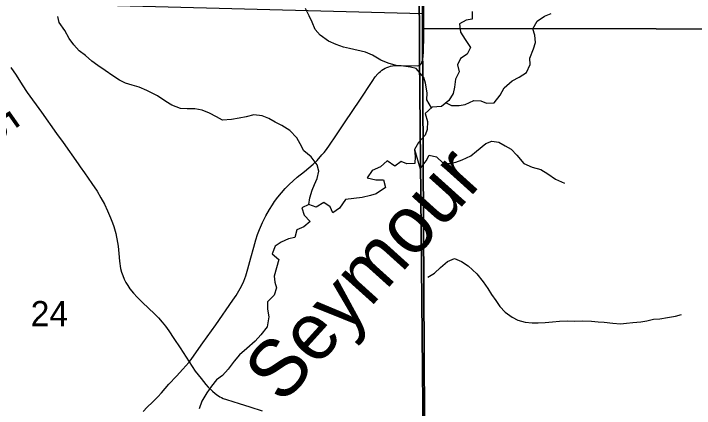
# Model space of a CAD drawing. Extents: x 1874609 to 2204689, y 815661 to 1281160.
# Drawn here: x 2009363 to 2015341, y 1005693 to 1009164 of the extents above; entities that cross this region are included whole.
import ezdxf

# ---------------------------------------------------------------- set-up
doc = ezdxf.new("R2010")
doc.units = 0
for name, color, linetype in [('GM_X_County_Road', 7, 'Continuous'), ('GM_X_County_Road_Text', 7, 'Continuous'), ('GM_X_Minor_River', 7, 'Continuous'), ('GM_X_Minor_River_Text', 7, 'Continuous'), ('GM_X_Section', 7, 'Continuous'), ('GM_X_Section_Text', 7, 'Continuous'), ('GM_X_Township', 7, 'Continuous'), ('GM_X_Township_Road', 7, 'Continuous')]:
    doc.layers.add(name, color=color, linetype=linetype)

msp = doc.modelspace()

# ---------------------------------------------------------------- linework, layer by layer
at = {"layer": 'GM_X_County_Road'}
for points in [[(2009340, 1008689.6), (2009385.4, 1008621.4), (2009438, 1008538.4), (2009483.6, 1008470.2), (2009607.4, 1008296.7), (2009739.6, 1008110), (2009797.7, 1008030.5), (2009929.1, 1007842.9), (2009948.2, 1007816.9), (2009985.9, 1007764), (2010050.9, 1007669.7), (2010096.2, 1007601.5), (2010129.5, 1007545.4), (2010160.3, 1007487.9), (2010188.8, 1007429.2), (2010215.2, 1007369.7), (2010232.9, 1007324.4), (2010242.7, 1007293.6), (2010259.6, 1007230.5), (2010276.7, 1007151), (2010281.4, 1007119.1), (2010286.6, 1007054.2), (2010293.3, 1006988.7), (2010303, 1006923.7), (2010310.4, 1006891.4), (2010321.1, 1006860.1), (2010334.5, 1006829.9), (2010349.6, 1006800.7), (2010366.4, 1006772.5), (2010385.1, 1006745.5), (2010415.8, 1006707.2), (2010448.6, 1006670.8), (2010494.6, 1006624.1), (2010601.1, 1006522.9), (2010634.9, 1006488.4), (2010667, 1006452.4), (2010697.6, 1006414.5), (2010726.3, 1006375.3), (2010771.6, 1006308.1), (2010825, 1006226.2), (2010904.8, 1006101.4)], [(2010904.8, 1006101.4), (2010930.8, 1006060.8), (2010959, 1006020.5), (2011008.8, 1005955.1), (2011050.3, 1005904), (2011072.6, 1005879.5), (2011108.5, 1005845.5), (2011133.4, 1005824.1), (2011146.3, 1005813.8), (2011174, 1005795.2), (2011188.6, 1005787.5), (2011203.6, 1005780.7), (2011233.9, 1005769.6), (2011343.3, 1005734.7), (2011437.3, 1005705.6), (2011546.5, 1005671.2)]]:
    msp.add_lwpolyline(points, dxfattribs=at)
at = {"layer": 'GM_X_Minor_River'}
for points in [[(2013032, 1008335.8), (2012991, 1008404.8), (2012995.2, 1008468.9), (2012981.5, 1008551.2), (2012965.7, 1008603.5), (2012897.8, 1008680), (2012847.7, 1008694.3), (2012785.6, 1008700.6), (2012721.5, 1008706.9), (2012651.4, 1008727.2), (2012589.3, 1008755.6), (2012513.3, 1008800.1), (2012453.3, 1008824.4), (2012313.1, 1008857.2), (2012261, 1008869.4), (2012197, 1008891.8), (2012126.9, 1008922.2), (2012054.9, 1008974.7), (2012011, 1009025), (2011985.2, 1009089.3), (2011959.3, 1009145.6), (2011927.5, 1009209.9)], [(2013390.7, 1009183.4), (2013390.4, 1009115.2), (2013336.3, 1009107.4), (2013278, 1009073.5), (2013287.8, 1009001.3), (2013329.7, 1008936.9), (2013375.5, 1008866.5), (2013347.2, 1008808.4), (2013287, 1008768.6), (2013260.7, 1008712.5), (2013276.5, 1008652.2), (2013242.2, 1008586.2), (2013236, 1008516), (2013223.7, 1008461.9), (2013185.4, 1008399.9), (2013121.1, 1008348), (2013038.9, 1008342.3), (2012978.6, 1008284.4), (2012998.3, 1008214.1), (2012994.1, 1008145.9), (2012977.9, 1008095.8), (2012917.5, 1008029.9), (2012883.2, 1007967.9)], [(2013160.4, 1008379.7), (2013209.3, 1008355.6), (2013275.5, 1008355.3), (2013327.6, 1008365.1), (2013403.9, 1008398.9), (2013466, 1008396.6), (2013516.1, 1008376.3), (2013582.3, 1008380), (2013636.6, 1008448), (2013670.9, 1008510.1), (2013741.3, 1008573.9), (2013801.5, 1008603.8), (2013867.8, 1008647.6), (2013898.2, 1008715.7), (2013896.3, 1008771.9), (2013928.7, 1008854), (2013947, 1008910.1), (2013941.2, 1008974.3), (2013923.3, 1009030.5), (2013959.6, 1009098.6), (2014025.9, 1009140.4), (2014082.2, 1009164.2)], [(2011955.4, 1007486.5), (2011963.7, 1007544.7), (2011983.9, 1007610.8), (2012004.2, 1007660.8), (2012028.4, 1007712.9), (2012044.7, 1007779), (2012028.8, 1007835.2), (2011977, 1007903.7), (2011911, 1007956.1), (2011879.1, 1008018.5), (2011851.3, 1008070.8), (2011789.3, 1008135.2), (2011717.3, 1008179.7), (2011661.3, 1008210), (2011603.3, 1008242.4), (2011547.3, 1008266.7), (2011473.1, 1008273.1), (2011404.9, 1008257.3), (2011342.7, 1008243.5), (2011276.5, 1008233.8), (2011196.3, 1008228.1), (2011146.3, 1008256.5), (2011082.3, 1008288.8), (2011018.3, 1008315.2), (2010954.1, 1008325.5), (2010888, 1008327.8), (2010827.9, 1008330.1), (2010751.8, 1008360.5), (2010699.8, 1008390.8), (2010625.8, 1008441.3), (2010531.8, 1008487.9), (2010465.7, 1008516.3), (2010403.6, 1008534.6), (2010345.6, 1008552.9), (2010293.6, 1008579.2), (2010235.6, 1008615.6), (2010167.6, 1008664), (2010103.6, 1008708.5), (2010051.6, 1008746.8), (2009993.7, 1008795.2), (2009939.7, 1008837.6), (2009891.8, 1008890), (2009849.9, 1008946.3), (2009814, 1009014.7), (2009764.2, 1009085.1), (2009752.3, 1009137.3)], [(2012883.2, 1007967.9), (2012932.7, 1007799.1), (2012985.1, 1007869.1), (2013013.3, 1007919.2), (2013075.4, 1007904.8), (2013135.4, 1007848.4), (2013187.5, 1007846.2), (2013245.6, 1007857.9), (2013301.8, 1007877.7), (2013378.1, 1007913.5), (2013428.4, 1007955.4), (2013508.8, 1008021.3), (2013563, 1008041.1), (2013623.1, 1008032.8), (2013679.1, 1008002.4), (2013731.1, 1007972.1), (2013781.1, 1007919.8), (2013845, 1007847.2), (2013917, 1007812.8), (2013993.1, 1007794.4), (2014053.1, 1007756), (2014123.1, 1007707.6), (2014201.1, 1007673.1)], [(2012883.2, 1007967.9), (2012889, 1007907.7), (2012886.8, 1007847.5), (2012816.6, 1007843.8), (2012766.6, 1007864.1), (2012710.3, 1007822.2), (2012644.3, 1007868.6), (2012586, 1007816.7), (2012511.7, 1007784.9), (2012467.4, 1007720.9), (2012543.5, 1007702.6), (2012611.7, 1007702.3), (2012627.5, 1007634), (2012547.1, 1007580.2), (2012496.9, 1007564.3), (2012424.7, 1007546.6), (2012350.5, 1007538.9), (2012278.3, 1007529.2), (2012225.9, 1007453.2), (2012167.6, 1007413.3), (2012141.8, 1007465.6), (2012087.8, 1007502), (2012019.5, 1007462.1), (2011955.4, 1007486.5), (2011895.2, 1007456.7), (2011915, 1007392.4), (2011966.9, 1007336), (2011910.6, 1007290.1), (2011850.4, 1007264.3), (2011832.1, 1007194.1), (2011778, 1007182.3), (2011713.7, 1007154.5), (2011659.5, 1007118.7), (2011633.2, 1007052.6), (2011693.1, 1007002.2), (2011672.8, 1006928), (2011650.5, 1006855.9), (2011658.3, 1006803.7), (2011672.2, 1006753.5), (2011651.9, 1006687.4), (2011591.6, 1006629.5), (2011591.3, 1006565.3), (2011605.1, 1006499), (2011590.8, 1006408.8), (2011534.4, 1006340.8), (2011484.1, 1006282.9), (2011411.7, 1006219), (2011347.4, 1006165.1), (2011301.1, 1006107.1), (2011248.7, 1006037.2), (2011196.4, 1005983.2), (2011146.1, 1005945.3), (2011099.8, 1005887.3), (2011059.5, 1005829.4), (2011017.2, 1005757.3), (2010992.9, 1005689.2)], [(2013001.5, 1006847.9), (2013057.8, 1006881.8), (2013112.1, 1006931.7), (2013172.4, 1006985.6), (2013234.6, 1007009.4), (2013296.7, 1006983), (2013354.7, 1006946.6), (2013430.6, 1006876.1), (2013486.4, 1006805.6), (2013526.3, 1006747.3), (2013560.2, 1006692.9), (2013598.1, 1006640.6), (2013634, 1006588.3), (2013679.9, 1006537.9), (2013739.9, 1006493.5), (2013791.9, 1006467.2), (2013856, 1006450.9), (2013916.1, 1006444.6), (2013970.3, 1006446.4), (2014030.4, 1006448.1), (2014096.6, 1006453.8), (2014156.7, 1006459.6), (2014226.9, 1006461.3), (2014285, 1006461), (2014357.2, 1006462.7), (2014437.4, 1006460.3), (2014497.5, 1006454.1), (2014549.6, 1006449.8), (2014623.7, 1006443.5), (2014691.9, 1006437.1), (2014746, 1006440.9), (2014802.1, 1006446.7), (2014870.3, 1006454.4), (2014924.5, 1006462.2), (2014982.6, 1006476), (2015038.8, 1006481.7), (2015105, 1006491.5), (2015175.2, 1006505.2), (2015227.3, 1006517)]]:
    msp.add_lwpolyline(points, dxfattribs=at)
at = {"layer": 'GM_X_Section'}
for points in [[(2012933.5, 1014271.1), (2019482.8, 1014226.8), (2019429.8, 1008990.1), (2019105.5, 1009025.5), (2012952.5, 1009034.6), (2012954.3, 1009164.7)], [(2012954.3, 1009164.7), (2012952.5, 1009034.6), (2012981.3, 1003882.2), (2008513, 1003978.9), (2007610.6, 1003961), (2007591.4, 1009307.4)], [(2019429.8, 1008990.1), (2019258.7, 1003713.2), (2012971.6, 1003772.1), (2012981.3, 1003882.2), (2012952.5, 1009034.6), (2019105.5, 1009025.5)]]:
    msp.add_lwpolyline(points, close=True, dxfattribs=at)
at = {"layer": 'GM_X_Township'}
for points in [[(2012830.6, 1025241.9), (2012842.5, 1023547.9), (2012864.5, 1022216.8), (2012856.4, 1019843.6), (2012859.4, 1019535.5), (2012901.8, 1015157.2), (2012905.1, 1014538.5), (2012905.6, 1014235.6), (2012920.4, 1010262.3), (2012927.2, 1008777.9), (2012961.7, 1005114.1), (2012977.9, 1002278.3), (2012966.8, 1001159.1), (2013012.1, 995874.2)], [(2013012.1, 995874.2), (2012966.8, 1001159.1), (2012977.9, 1002278.3), (2012961.7, 1005114.1), (2012927.2, 1008777.9), (2012920.4, 1010262.3), (2012905.6, 1014235.6), (2012905.1, 1014538.5), (2012901.8, 1015157.2), (2012859.4, 1019535.5), (2012856.4, 1019843.6), (2012864.5, 1022216.8), (2012842.5, 1023547.9), (2012830.6, 1025241.9), (2013359, 1025236.7), (2014559, 1025225.1), (2018880.2, 1025183.1), (2019554.9, 1025176.6), (2023338.3, 1025139.8), (2030477.9, 1025070.5), (2037504.4, 1025002.2)]]:
    msp.add_lwpolyline(points, dxfattribs=at)
at = {"layer": 'GM_X_Township_Road'}
for points in [[(2012928.3, 1008710.1), (2012936.4, 1008715.5), (2012943.8, 1008724.9), (2012949.2, 1008735.7), (2012955.2, 1008751.2), (2012957.7, 1008768), (2012960, 1008784.2), (2012962.8, 1008833.3), (2012964.1, 1008964.5), (2012965.4, 1009128.4), (2012964.2, 1009243), (2012955.2, 1009488.5), (2012953.8, 1009619.4), (2012951.4, 1009864.8), (2012948, 1009995.8), (2012946.8, 1010061.1), (2012943.2, 1010224.1), (2012941.7, 1010289.9)], [(2010904.8, 1006101.4), (2010921.6, 1006121.6), (2010950.1, 1006161), (2011024.6, 1006269), (2011139.4, 1006428.8), (2011289.1, 1006644), (2011316.2, 1006684.5), (2011341.5, 1006725.6), (2011364.4, 1006768.3), (2011384.4, 1006812.7), (2011401.3, 1006858.6), (2011420.5, 1006920.9), (2011445.8, 1007015.8), (2011471.9, 1007110.8), (2011490.7, 1007173.7), (2011506.1, 1007220.4), (2011523.5, 1007266.4), (2011549.5, 1007326.4), (2011578.7, 1007384.9), (2011610.9, 1007441.8), (2011636.8, 1007483.5), (2011655.2, 1007510.6), (2011684.8, 1007550.2), (2011716.1, 1007588.3), (2011748.6, 1007625.2), (2011782.2, 1007661), (2011817.6, 1007694.8), (2011854.6, 1007726.6), (2011918.5, 1007776.8), (2011956.6, 1007807.4), (2011993.2, 1007839.6), (2012027.5, 1007873.9), (2012069.8, 1007921.4), (2012090, 1007943.8), (2012110, 1007968.6), (2012137.8, 1008008.2), (2012191.6, 1008090.5), (2012273.9, 1008213.2), (2012402.7, 1008402.9), (2012511.5, 1008566.6), (2012539.5, 1008607.3), (2012560.4, 1008633.2), (2012572.1, 1008645.1), (2012584.6, 1008656.3), (2012597.8, 1008666.5), (2012611.7, 1008675.7), (2012626.5, 1008683.8), (2012641.8, 1008690.7), (2012657.1, 1008697.3), (2012673.2, 1008702.7), (2012690, 1008706.1), (2012721, 1008707.4), (2012766.8, 1008708.1), (2012908.1, 1008705.4), (2012920.9, 1008707.4), (2012928.3, 1008710.1)], [(2010502.1, 1005666.9), (2010536, 1005702.7), (2010583.6, 1005748.4), (2010595.3, 1005759.8), (2010609.4, 1005774.4), (2010629.2, 1005795), (2010662.3, 1005831), (2010727, 1005904.4), (2010793.5, 1005976.4), (2010848.3, 1006036.6), (2010901, 1006096.8), (2010904.8, 1006101.4)]]:
    msp.add_lwpolyline(points, dxfattribs=at)

# ---------------------------------------------------------------- texts
at = {"layer": 'GM_X_County_Road_Text'}
msp.add_text('5', height=300, rotation=305.04917, dxfattribs=at).set_placement((2009063.6, 1008162.5))
at = {"layer": 'GM_X_Minor_River_Text'}
msp.add_text('Seymour', height=500.14, rotation=47.93397, dxfattribs=at).set_placement((2011722.6, 1005719.9))
at = {"layer": 'GM_X_Section_Text'}
msp.add_text('24', height=221, rotation=0.00001, dxfattribs=at).set_placement((2009513.2, 1006415.8))

doc.saveas('drawing.dxf')
